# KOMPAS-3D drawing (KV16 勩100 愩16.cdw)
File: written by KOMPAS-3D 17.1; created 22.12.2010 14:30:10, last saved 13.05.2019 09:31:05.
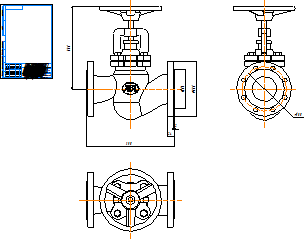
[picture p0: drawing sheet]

Title block, sheet 1: name: KV16 Ду100 Ру16; material: Внимание! Данный продукт является объектом авторского права ООО «Торговый Дом АДЛ». / Запрещается изменение, копирование, распространение / (в том числе путем копирования на другие сайты и ресурсы в Интернете) / или любое иное использование информации и объектов без предварительного / согласия правообладателя (ООО «Торговый Дом АДЛ»).; scale: 1:1; sheets: 1; organisation: ООО "Торговый дом АДЛ"; sheet format: A4; stored path: \\adlc.lan\data\АДЛ_ПКД\3D-модели\ADL production\Вентили ГРАНВЕНТ\KV16\KOMPAS 2D\KV16 Ду100 Ру16.cdw

Views: Спереди 1, Проекционный вид 2, Проекционный вид 3
Dimensions and other numbers on the sheet: 156; 220; 2; 24; 350; 339; 180; 1:1; 1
